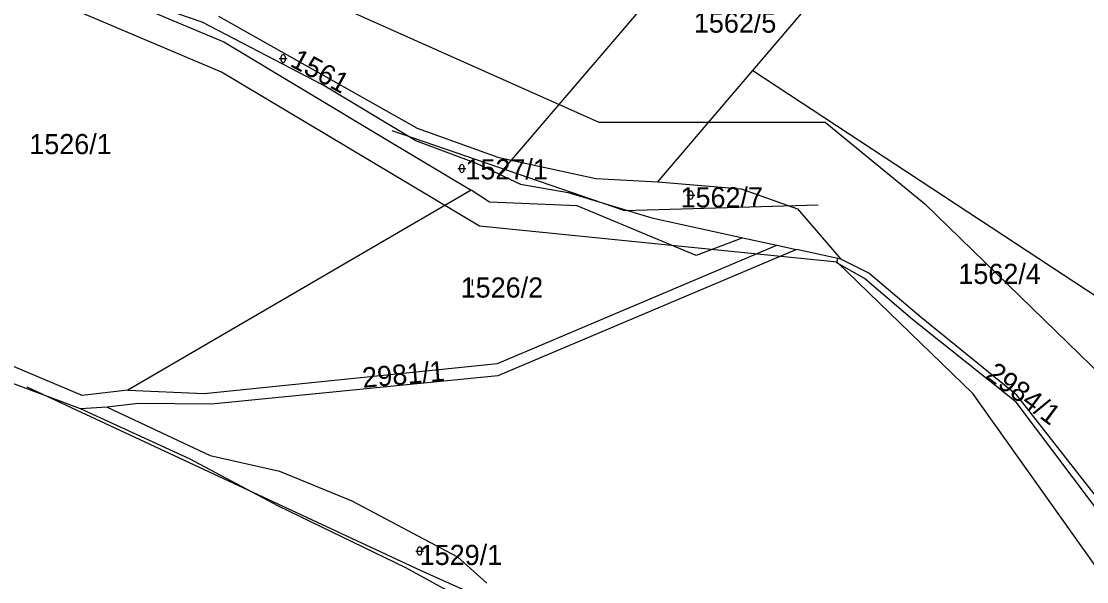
# Model space of a CAD drawing. Extents: x -564810 to -550519, y -1045831 to -1034011.
# Drawn here: x -553619.6 to -553350.1, y -1038653.6 to -1038511.8 of the extents above; entities that cross this region are included whole.
import ezdxf

# ---------------------------------------------------------------- set-up
doc = ezdxf.new("R2010")
doc.units = 0
for name, color, linetype in [('Biokoridory', 7, 'Continuous'), ('Interakční prvky', 7, 'Continuous'), ('KN stav', 7, 'Continuous'), ('Parcelní čísla', 7, 'Continuous'), ('zamokř ploch', 7, 'Continuous')]:
    doc.layers.add(name, color=color, linetype=linetype)

msp = doc.modelspace()

# ---------------------------------------------------------------- linework, layer by layer
at = {"layer": 'Biokoridory'}
for points in [[(-553000.91, -1038914.04), (-553087.95, -1038915.18), (-553123.45, -1038910.6), (-553193.31, -1038891.13), (-553274.62, -1038908.31), (-553272.33, -1038870.52), (-553294.09, -1038791.5), (-553310.12, -1038718.21), (-553347.91, -1038649.49), (-553378.83, -1038605.97), (-553413.19, -1038572.76), (-553503.66, -1038563.6), (-553568.94, -1038524.66), (-553696.06, -1038470.84)], [(-553607.45, -1038484.68), (-553537.59, -1038508.73), (-553473.46, -1038537.36), (-553416.19, -1038537.36), (-553391, -1038557.98), (-553309.69, -1038637), (-553283.35, -1038697.7), (-553266.17, -1038797.33), (-553257.01, -1038814.51)]]:
    msp.add_lwpolyline(points, dxfattribs=at)
at = {"layer": 'Interakční prvky'}
for points in [[(-553525.84, -1038539.47), (-553467.01, -1038559.68), (-553417.99, -1038558.2)], [(-553618.25, -1038604.27), (-553518.71, -1038650.64), (-553455.13, -1038679.17)]]:
    msp.add_lwpolyline(points, dxfattribs=at)
at = {"layer": 'KN stav'}
for p, q in [((-553433.35, -1038474.19), (-553495.71, -1038546.93)), ((-553434.49, -1038524.24), (-553399.41, -1038483.09)), ((-553609.82, -1038499.62), (-553568.38, -1038517.05)), ((-553573.81, -1038512.08), (-553609.82, -1038499.62)), ((-553569.72, -1038510.56), (-553519.49, -1038538.86)), ((-553543.27, -1038527.99), (-553573.81, -1038512.08)), ((-553568.38, -1038517.05), (-553527.38, -1038541.65)), ((-553458.58, -1038552.42), (-553434.49, -1038524.24)), ((-553434.49, -1038524.24), (-553323.03, -1038597.55)), ((-553519.75, -1038542.06), (-553543.27, -1038527.99)), ((-553519.49, -1038538.86), (-553499.08, -1038546.2)), ((-553527.38, -1038541.65), (-553505.81, -1038554.55)), ((-553504.47, -1038547.81), (-553519.75, -1038542.06)), ((-553499.08, -1038546.2), (-553495.71, -1038546.93)), ((-553498.74, -1038550.46), (-553504.47, -1038547.81)), ((-553495.71, -1038546.93), (-553498.74, -1038550.46)), ((-553495.71, -1038546.93), (-553485.86, -1038549.08)), ((-553485.86, -1038549.08), (-553474.26, -1038551.6)), ((-553498.74, -1038550.46), (-553493.27, -1038552.99)), ((-553474.26, -1038551.6), (-553458.58, -1038552.42)), ((-553505.81, -1038554.55), (-553592.66, -1038605.14)), ((-553501.13, -1038557.55), (-553505.81, -1038554.55)), ((-553493.27, -1038552.99), (-553481.29, -1038555.09)), ((-553458.58, -1038552.42), (-553437.48, -1038554.16)), ((-553437.48, -1038554.16), (-553423.22, -1038559.23)), ((-553481.29, -1038555.09), (-553460.08, -1038561.53)), ((-553478.99, -1038558.52), (-553501.13, -1038557.55)), ((-553448.87, -1038571.07), (-553478.99, -1038558.52)), ((-553423.22, -1038559.23), (-553412.29, -1038571.98)), ((-553460.08, -1038561.53), (-553437.08, -1038566.56)), ((-553437.08, -1038566.56), (-553448.87, -1038571.07)), ((-553437.08, -1038566.56), (-553428.42, -1038568.45)), ((-553499.15, -1038598.34), (-553428.42, -1038568.45)), ((-553423.45, -1038569.54), (-553499.06, -1038601.52)), ((-553428.42, -1038568.45), (-553423.45, -1038569.54)), ((-553412.99, -1038571.83), (-553423.45, -1038569.54)), ((-553413.29, -1038572.94), (-553412.99, -1038571.83)), ((-553406.31, -1038576.85), (-553413.29, -1038572.94)), ((-553412.29, -1038571.98), (-553412.99, -1038571.83)), ((-553405.14, -1038575.49), (-553412.29, -1038571.98)), ((-553391.97, -1038586.72), (-553405.14, -1038575.49)), ((-553394.09, -1038587.24), (-553406.31, -1038576.85)), ((-553367.71, -1038606.36), (-553391.97, -1038586.72)), ((-553367.94, -1038608.18), (-553394.09, -1038587.24)), ((-553604.22, -1038606.45), (-553623.21, -1038598.47)), ((-553573.37, -1038605.92), (-553499.15, -1038598.34)), ((-553604.67, -1038609.87), (-553624.42, -1038602.42)), ((-553499.06, -1038601.52), (-553571.49, -1038608.68)), ((-553592.66, -1038605.14), (-553604.22, -1038606.45)), ((-553592.66, -1038605.14), (-553573.37, -1038605.92)), ((-553340.59, -1038644.4), (-553367.94, -1038608.18)), ((-553339.05, -1038643.1), (-553367.71, -1038606.36)), ((-553597.86, -1038609.43), (-553604.67, -1038609.87)), ((-553577.02, -1038622.48), (-553604.67, -1038609.87)), ((-553589.97, -1038608.47), (-553597.86, -1038609.43)), ((-553597.86, -1038609.43), (-553571.85, -1038621.65)), ((-553571.49, -1038608.68), (-553589.97, -1038608.47)), ((-553571.85, -1038621.65), (-553554.3, -1038625.6)), ((-553554.53, -1038634.42), (-553577.02, -1038622.48)), ((-553554.3, -1038625.6), (-553535.99, -1038633.13)), ((-553522.31, -1038650.08), (-553554.53, -1038634.42)), ((-553535.99, -1038633.13), (-553509.24, -1038647.27)), ((-553509.24, -1038647.27), (-553501.87, -1038653.96)), ((-553498.53, -1038663.01), (-553522.31, -1038650.08))]:
    msp.add_line(p, q, dxfattribs=at)
at = {"layer": 'zamokř ploch'}
for p, q in [((-553554.36, -1038521.26), (-553552.36, -1038521.26)), ((-553553.86, -1038521.76), (-553553.86, -1038520.76)), ((-553552.86, -1038520.76), (-553552.86, -1038521.76)), ((-553509.13, -1038549.05), (-553507.13, -1038549.05)), ((-553508.63, -1038549.55), (-553508.63, -1038548.55)), ((-553507.63, -1038548.55), (-553507.63, -1038549.55)), ((-553451.23, -1038555.78), (-553449.23, -1038555.78)), ((-553450.73, -1038556.28), (-553450.73, -1038555.28)), ((-553449.73, -1038555.28), (-553449.73, -1038556.28)), ((-553506.54, -1038577.15), (-553506.54, -1038578.65)), ((-553505.54, -1038577.15), (-553505.54, -1038578.65)), ((-553519.83, -1038645.8), (-553517.83, -1038645.8)), ((-553519.33, -1038646.3), (-553519.33, -1038645.3)), ((-553518.33, -1038645.3), (-553518.33, -1038646.3))]:
    msp.add_line(p, q, dxfattribs=at)
for centre, start, end in [((-553553.36, -1038520.76), 0, 180), ((-553553.36, -1038521.76), 180, 0), ((-553508.13, -1038548.55), 0, 180), ((-553508.13, -1038549.55), 180, 0), ((-553450.24, -1038555.28), 0, 180), ((-553450.24, -1038556.28), 180, 0), ((-553518.83, -1038645.3), 0, 180), ((-553518.83, -1038646.3), 180, 0)]:
    msp.add_arc(centre, 0.5, start, end, dxfattribs=at)

# ---------------------------------------------------------------- texts
at = {"layer": 'Parcelní čísla'}
for s, p in [('1562/5', (-553449.44, -1038514.7)), ('1526/1', (-553617.59, -1038545.42)), ('1527/1', (-553507.24, -1038551.8)), ('1562/7', (-553452.82, -1038558.89)), ('1562/4', (-553382.53, -1038578.25)), ('1526/2', (-553508.44, -1038581.7)), ('1529/1', (-553518.81, -1038649.33))]:
    msp.add_text(s, height=5.1, dxfattribs=at).set_placement(p)
for s, rotation, p in [('1561', 331.6208, (-553551.86, -1038523.03)), ('2981/1', 4.9271, (-553533.13, -1038604.53)), ('2984/1', 323.3463, (-553375.91, -1038601.77))]:
    msp.add_text(s, height=5.1, rotation=rotation, dxfattribs=at).set_placement(p)

doc.saveas('drawing.dxf')
